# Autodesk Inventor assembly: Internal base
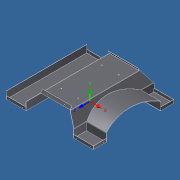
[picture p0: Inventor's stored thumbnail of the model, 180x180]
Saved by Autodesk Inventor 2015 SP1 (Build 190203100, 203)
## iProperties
Category: Mechanical Engineering Drawing and Design - CADD
Manager: Fábio Ricardo de Oliveira Souza
Company: SENAI - Serviço Nacional de Aprendizagem Industrial
Created: 2011-06
Part Number: Internal base
Document SubType Name: Weldment
Designer: Guilherme Augusto Franco de Souza
Engineer: George Geraldo de Oliveia Silva
Authority: Fábio Ricardo de Oliveira Soza
Weld Material: Welded Stainless Steel, 440C
Description: Sub-assembly
Subject: WorldSkill 2011 - London, England
Author: Guilherme Augusto Franco de Souza
Revision Number: 00
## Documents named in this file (3)
- E:\Visitor Experience Project\WSI2015 - Visitor Experience Project\#46- Sheet Metal Technology\01- 3D Models\Outodoor Heater\2- Assemblies\Internal base.iam
- E:\Visitor Experience Project\WSI2015 - Visitor Experience Project\#46- Sheet Metal Technology\01- 3D Models\Outodoor Heater\1- Parts\Internal base.ipt
- E:\Visitor Experience Project\WSI2015 - Visitor Experience Project\#46- Sheet Metal Technology\01- 3D Models\Outodoor Heater\1- Parts\Internal base hat.ipt
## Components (2 placed, 2 different names)
1. Internal base:1 — Flush:3
2. Internal base hat:1 — Flush:3
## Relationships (1: Flush 1)
- Flush:3: Internal base:1 ↔ Internal base hat:1
